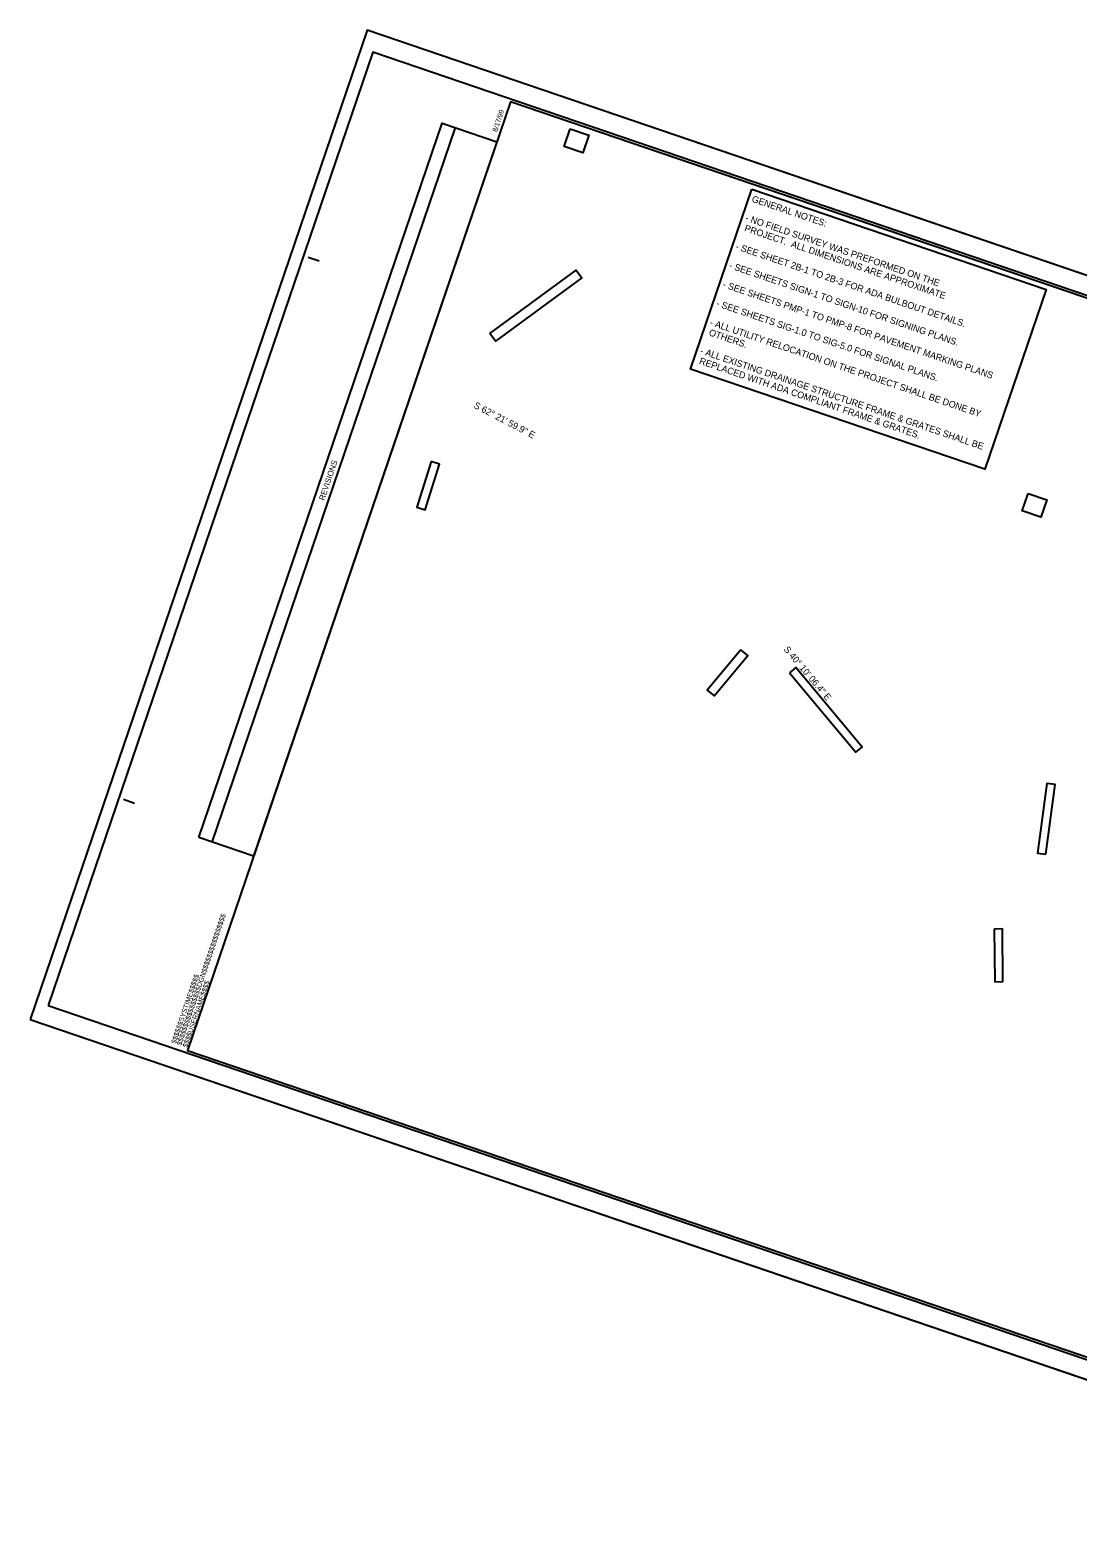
# Model space of a CAD drawing. Extents: x 927646 to 937215, y 684320 to 686920.
# Drawn here: x 927646 to 928744, y 685341 to 686920 of the extents above; entities that cross this region are included whole.
import ezdxf

# ---------------------------------------------------------------- set-up
doc = ezdxf.new("R2010")
doc.units = 0
for name, color, linetype in [('Exist Horizontal Alignment Direction Label', 7, 'Continuous'), ('Exist Horizontal Alignment Station Label', 7, 'Continuous'), ('Prop DSN Text', 7, 'Continuous'), ('Sheet Cutting Line CELL', 7, 'Continuous'), ('Sheet Plan CELL', 7, 'Continuous'), ('Sheet Plan Layout CELL', 7, 'Continuous'), ('Sheet Plot Border Inside CELL', 7, 'Continuous'), ('Sheet Plot Border Outside CELL', 7, 'Continuous')]:
    doc.layers.add(name, color=color, linetype=linetype)

msp = doc.modelspace()

# ---------------------------------------------------------------- linework, layer by layer
at = {"layer": 'Exist Horizontal Alignment Station Label'}
for points in [[(928211.6, 686816.9), (928231.2, 686810.2), (928224.9, 686791.9), (928205.3, 686798.5)], [(928127.6, 686602.7), (928217.9, 686669), (928223.8, 686660.9), (928133.5, 686594.7)], [(928065.9, 686468.3), (928051.1, 686420.7), (928059.9, 686418), (928074.7, 686465.5)], [(928691.7, 686435), (928711.3, 686428.3), (928705.1, 686410), (928685.4, 686416.7)], [(928390.7, 686271.2), (928355.4, 686228.8), (928362.5, 686222.9), (928397.9, 686265.2)], [(928441.7, 686247.1), (928511.1, 686163.9), (928517.6, 686169.3), (928448.2, 686252.6)], [(928710.1, 686057.1), (928720, 686130), (928711.4, 686131.2), (928701.6, 686058.2)], [(928656.2, 685978.7), (928656.7, 685923.5), (928665.3, 685923.6), (928664.7, 685978.8)]]:
    msp.add_lwpolyline(points, close=True, dxfattribs=at)
at = {"layer": 'Prop DSN Text'}
msp.add_lwpolyline([(928402.1, 686753.7), (928710.4, 686648.6), (928646.2, 686460.3), (928337.9, 686565.3)], close=True, dxfattribs=at)
at = {"layer": 'Sheet Cutting Line CELL'}
for p, q in [((927999, 686920.3), (927645.8, 685883.9)), ((929592.5, 686377.4), (927999, 686920.3)), ((927645.8, 685883.9), (929239.3, 685340.9))]:
    msp.add_line(p, q, dxfattribs=at)
at = {"layer": 'Sheet Plan CELL'}
for p, q in [((928149.3, 686845.4), (928149.3, 686845.4)), ((927836.5, 686069.8), (928091.5, 686818.2)), ((927937, 686682.6), (927948.8, 686678.6)), ((927743.5, 686114.7), (927755.3, 686110.7)), ((927810.6, 685851.5), (927810.6, 685851.5))]:
    msp.add_line(p, q, dxfattribs=at)
for points in [[(929569.2, 686361.5), (928149.3, 686845.4), (927810.6, 685851.5), (929230.5, 685367.7)], [(927822.7, 686074.5), (928077.7, 686822.9), (928135, 686803.4), (927880, 686055)]]:
    msp.add_lwpolyline(points, close=True, dxfattribs=at)
at = {"layer": 'Sheet Plan Layout CELL'}
msp.add_lwpolyline([(928149.3, 686845.3), (927810.6, 685851.5), (929230.5, 685367.7), (929500.9, 686161.4), (929274.5, 686238.5), (929342.7, 686438.7)], close=True, dxfattribs=at)
at = {"layer": 'Sheet Plot Border Inside CELL'}
msp.add_lwpolyline([(927664.5, 685898.6), (929241.5, 685361.3), (929581.8, 686359.9), (928004.8, 686897.2)], close=True, dxfattribs=at)
at = {"layer": 'Sheet Plot Border Outside CELL'}
msp.add_lwpolyline([(927645.8, 685883.9), (929239.3, 685340.9), (929592.5, 686377.4), (927999, 686920.3)], close=True, dxfattribs=at)

# ---------------------------------------------------------------- texts
at = {"layer": 'Exist Horizontal Alignment Direction Label'}
for s, rotation, p in [('S 62%%d 21\' 59.9" E', 332.3666, (928110, 686525.1)), ('S 40%%d 10\' 06.4" E', 310.1684, (928435, 686271.4))]:
    msp.add_text(s, height=7, rotation=rotation, dxfattribs=at).set_placement(p)
at = {"layer": 'Prop DSN Text'}
for s, p in [('GENERAL NOTES:', (928401.4, 686740.7)), ('- NO FIELD SURVEY WAS PREFORMED ON THE ', (928394.7, 686720.9)), (' PROJECT.  ALL DIMENSIONS ARE APPROXIMATE', (928391.3, 686710.9)), ('- SEE SHEET 2B-1 TO 2B-3 FOR ADA BULBOUT DETAILS.', (928384.5, 686691)), ('- SEE SHEETS SIGN-1 TO SIGN-10 FOR SIGNING PLANS.', (928377.7, 686671.2)), ('- SEE SHEETS PMP-1 TO PMP-8 FOR PAVEMENT MARKING PLANS  ', (928371, 686651.3)), ('- SEE SHEETS SIG-1.0 TO SIG-5.0 FOR SIGNAL PLANS.', (928364.2, 686631.4)), ('- ALL UTILITY RELOCATION ON THE PROJECT SHALL BE DONE BY ', (928357.4, 686611.5)), (' OTHERS.', (928354, 686601.6)), ('- ALL EXISTING DRAINAGE STRUCTURE FRAME & GRATES SHALL BE ', (928347.3, 686581.7)), (' REPLACED WITH ADA COMPLIANT FRAME & GRATES.', (928343.9, 686571.8))]:
    msp.add_text(s, height=7, rotation=341.1836, dxfattribs=at).set_placement(p)
at = {"layer": 'Sheet Plan CELL'}
for s, height, p in [('8/17/99', 5.25, (928134.9, 686813.1)), ('REVISIONS', 6, (927954, 686427.2)), ('$$$$$$$$$$$$$$$$DGN$$$$$$$$$$$$$$$$', 5.25, (927804.2, 685856.2)), ('$$$$$$SYSTIME$$$$$', 5.25, (927798.4, 685858.1)), ('$$$$USERNAME$$$$', 5.25, (927810.4, 685854.1))]:
    msp.add_text(s, height=height, rotation=71.1836, dxfattribs=at).set_placement(p)

doc.saveas('drawing.dxf')
